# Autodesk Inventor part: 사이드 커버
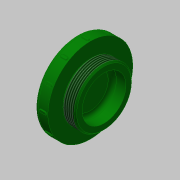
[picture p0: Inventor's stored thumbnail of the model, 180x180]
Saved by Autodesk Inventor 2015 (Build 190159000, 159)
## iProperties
Created: 2016-08
Part Number: 사이드 커버
Material: 스테인리스강
Document SubType Name: Modeling
Designer: mduedu
Density: 8.08 g/cm^3
Appearance: 진녹색
Author: mduedu
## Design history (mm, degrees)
sketch "스케치1"
  geometry: L1 (-5, 0)-(5, 0); L2 (-5, 0)-(-5, 31); L3 (-5, 31)-(5, 31); L4 (5, 31)-(5, 21); L5 (5, 21)-(15, 21); L6 (15, 21)-(15, 16); L7 (15, 16)-(5, 16); L8 (5, 16)-(5, 0); 2 further points
  constraints: 16 end point, 4 parallel, 2 perpendicular, 1 coincident, 1 collinear, 1 horizontal, 1 midpoint, 1 vertical
  dimensions: "d0" = 10 distance of L1.start L1.end; "d2" = 62 diameter of L3 L1; "d3" = 42 diameter of L5 L1; "d4" = 10 distance between parallel lines of L6 L8; "d5" = 5 distance of L5.end L6.end
revolve "회전1" sketch "스케치1" stored, may be unused: angle "d6" = 90 deg
fillet "모깎기1" dims "d7" = 3
sketch "스케치2"
  geometry: L1 (5, -31)-(5, 31) reference; L2 (5, 21)-(15, 21) reference; L3 (0, 0)-(5, 0); L4 (5, 21)-(6, 21); L5 (6, 21)-(6, 20); L6 (6, 20)-(5, 20); L7 (5, 20)-(5, 21)
  constraints: 10 end point, 2 parallel, 1 horizontal, 1 midpoint, 1 perpendicular
  dimensions: "d8" = 1 distance of L2.start L4.end; "d9" = 40 diameter of L6 L3
revolve "회전2" sketch "스케치2" stored, may be unused: angle "d10" = 90 deg
fillet "모깎기2" dims "d11" = 3
feature "스레드1" dims "d12" = 10, "d13" = 0
chamfer "모따기1" distance "d14" = 1; stored, may be unused: second distance "d15" = 2, angle "d16" = 45 deg
node "작업 평면1"
sketch "스케치3"
  geometry: L1 (1, -1)-(-4, -1); L2 (-4, -1)-(-4, 1); L3 (-4, 1)-(1, 1); L4 (1, 1)-(1, -1); 2 further points
  constraints: 8 end point, 2 parallel, 1 horizontal, 1 horizontal alignment, 1 midpoint, 1 perpendicular
  dimensions: "d18" = 2 distance of L3.end L1.start; "d20" = 5 distance of L1.start L1.end; "d21" = 1 distance from line of L4 point (0, 0)
extrude "돌출1" join sketch "스케치3" stored distance "d22" = 10; taper "d23" = 0 deg
fillet "모깎기3" dims "d24" = 1
fillet "모깎기4" dims "d25" = 0.2
sketch "스케치4"
  geometry: 2 further points
  constraints: 1 coincident, 1 other
feature "엠보싱1" sketch "스케치4" dims "d0" = 10, "d2" = 62, "d3" = 42, "d4" = 10, "d5" = 5, "d29" = 0.5, "d30" = 0
node "솔리드1"
pattern_circular "원형 패턴1" dims "d27" = 360 deg
other parameters: "d17" = 31.5
